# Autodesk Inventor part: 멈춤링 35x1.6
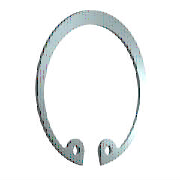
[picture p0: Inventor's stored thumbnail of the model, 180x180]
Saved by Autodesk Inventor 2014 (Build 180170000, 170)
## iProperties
IsCustomPart: 1
Created: 2012-02
Part Number: 멈춤링 35x1.6
Material: 강철, 연강
Description: 리테이닝 링(C형)
Document SubType Name: Modeling
Standard: KS B 1336
Designer: mduedu
Standards Organization: KS
Language: ko-KR
Size Designation: 35x1.6
Categories: <MemberInstance><Categories><Category DisplayName="샤프트 부품" InternalName="7f7aeb1f-a693-4053-b835-cee3144e0d98" Mnemonic="SHFT"><Category DisplayName="써클립" Inter
Density: 1 g/cm^3
Appearance: Blue - Wall Paint - Glossy
Author: mduedu
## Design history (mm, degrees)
sketch "스케치1"
  geometry: L1 (0, 15.113)-(0, -73.177) reference; L2 (-45.5, 0)-(45.5, 0) reference; L3 (-4.964, 1)-(1.502, 1); L4 (0, -2.5)-(-5.307, -2.5); L5 (0, -17.5)-(-8.583, -33.888); L6 (-8.583, -33.888)-(-21.772, -26.981); L7 (-7.377, -31.585)-(-17.631, -26.214); L8 (-5.162, -32.745)-(-6.29, -34.898); L9 (5.162, -32.745)-(6.29, -34.898); C1 r 1.25 at (-7.377, -31.585); C2 r 1.25 at (7.377, -31.585); A1 r 15.875 centre (0, -18.375) between (11.82, -28.972) and (-11.82, -28.972); A2 r 18.5 centre (0, -17.5) between (6.29, -34.898) and (-6.29, -34.898); A3 r 2.5 centre (-7.377, -31.585) between (-5.162, -32.745) and (-8.668, -29.444); A4 r 2.5 centre (-9.959, -27.303) between (-11.82, -28.972) and (-8.668, -29.444); A5 r 2.5 centre (9.959, -27.303) between (8.668, -29.444) and (11.82, -28.972); A6 r 2.5 centre (7.377, -31.585) between (8.668, -29.444) and (5.162, -32.745); 3 further points
  constraints: 15 point on circle, 14 end point, 9 symmetric about line, 8 centre point, 6 tangent, 4 coincident, 4 point on line, 3 perpendicular, 1 parallel, 4 other
  dimensions: "d8" = 0.875 distance of A1.centre L5.start (= 0.25 x SRB1); "d38" = 3.5 distance between parallel lines of L4 L3 (= SRB1); "d39" = 17.5 distance from line of L5.start L2 (= 0.5 x WD); "d43" = 18.5 radius of A2 (= 0.5 x ND); "d45" = 2.6 distance between parallel lines of L7 L6 (= 0.5 x SRB2); "d46" = 2.5 radius of A4 (= SD5); "d47" = 6.29 distance from line of L1 L8.end (= 0.17 x ND); "d48" = 2.5 diameter of C1 (= SD5); "d49" = 2.5 radius of A3 (= SD5)
extrude "본체" new body sketch "스케치1" distance "d2" = 1.6 (= SD); taper "d3" = 0 deg
workaxis "Work Axis1"
workaxis "Work Axis2"
workplane "Work Plane1"
body "Solid1"
other parameters: "WD" = 35 [user parameter; used in 3 equation terms], "SD" = 1.6 [user parameter; used in 1 equation term], "SRB1" = 3.5 [user parameter; used in 2 equation terms], "ND" = 37 [user parameter; used in 2 equation terms], "SRB2" = 5.2 [user parameter; used in 1 equation term], "SD5" = 2.5 [user parameter; used in 3 equation terms], "d50" = 0, "d51" = 0, "d52" = 0, "d53" = 0, "WDMIN" = 34 [user parameter], "SD6" = 37.8 [user parameter], "WDMAX" = 35 (= WD) [user parameter], "NND" = 35 (= WD) [user parameter]
